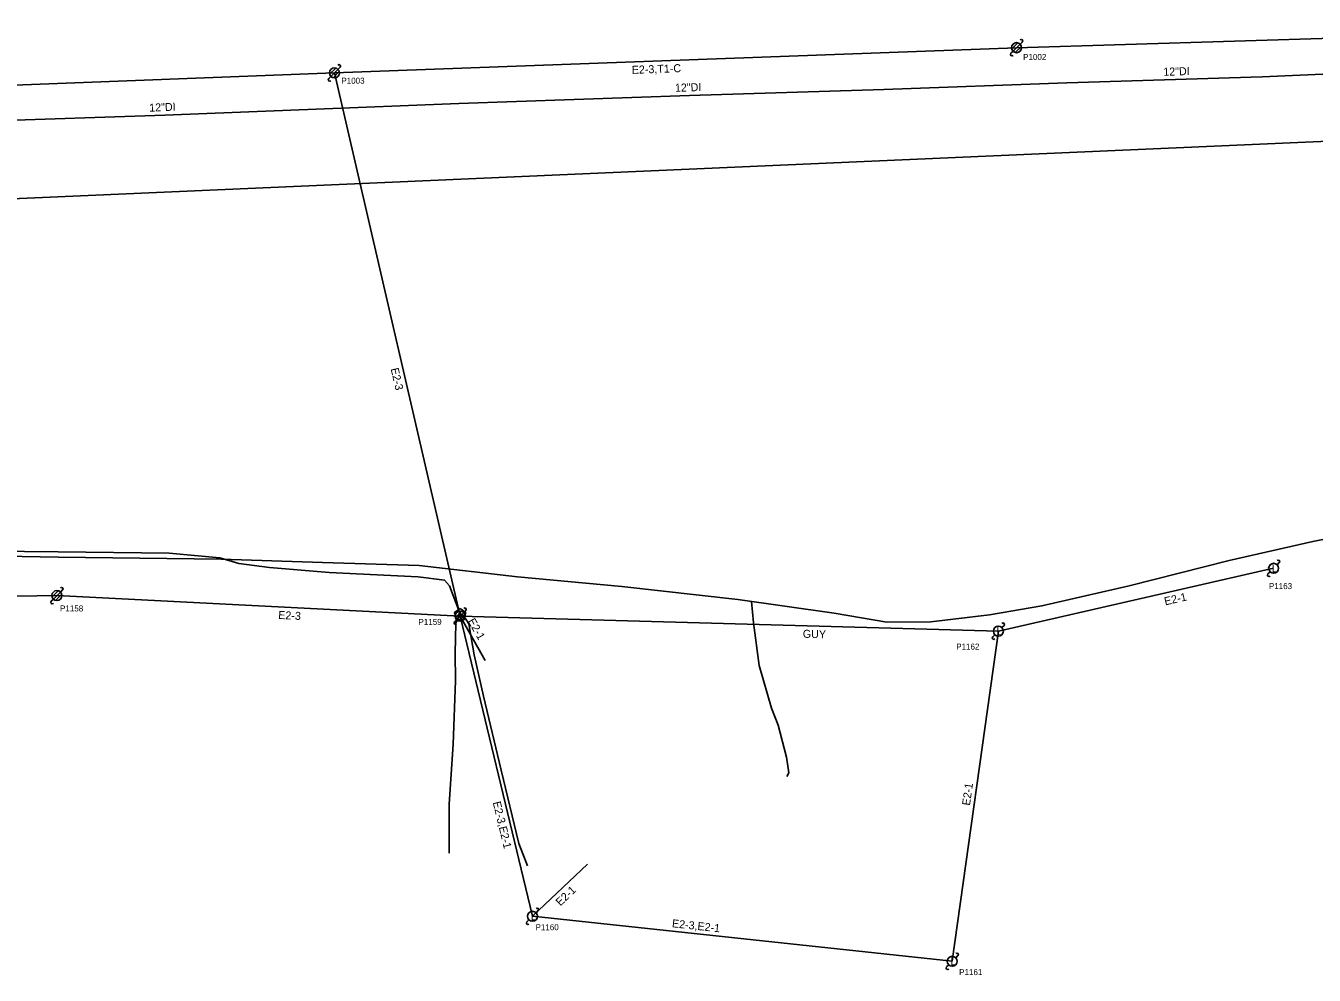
# Model space of a CAD drawing. Extents: x 1614474 to 1865144, y 1098877 to 1212550.
# Drawn here: x 1809717 to 1810361, y 1189759 to 1190233 of the extents above; entities that cross this region are included whole.
import ezdxf

# ---------------------------------------------------------------- set-up
doc = ezdxf.new("R2010")
doc.units = 0
for name, color, linetype in [('BFUSER_FIBERSPAN', 7, 'Continuous'), ('RD_EX_SU_Gas', 7, 'Continuous'), ('RD_EX_SU_H2O', 7, 'Continuous'), ('RD_EX_SU_Ovhd', 7, 'Continuous'), ('RD_EX_SU_Pole', 7, 'Continuous'), ('RD_EX_SU_Telecom', 7, 'Continuous'), ('RD_EX_SU_TX_H2O', 7, 'Continuous'), ('RD_EX_SU_TX_Pole', 7, 'Continuous')]:
    doc.layers.add(name, color=color, linetype=linetype)

# ---------------------------------------------------------------- blocks, each defined once
blk = doc.blocks.new('SUE_TPP')
at = {"layer": 'RD_EX_SU_Telecom'}
blk.add_lwpolyline([(0, 3), (-2.85, 0.93), (-1.76, -2.43), (1.76, -2.43), (2.85, 0.93)], close=True, dxfattribs=at)
blk.add_text('T', height=3.75, dxfattribs=at).set_placement((-1.25, -1.88))

msp = doc.modelspace()

# ---------------------------------------------------------------- linework, layer by layer
at = {"layer": 'BFUSER_FIBERSPAN'}
msp.add_line((1809476.93, 1190136.61), (1810575.1, 1190184.71), dxfattribs=at)
at = {"layer": 'RD_EX_SU_Gas'}
for points in [[(1809660.86, 1189969.17), (1809733.78, 1189967.7), (1809815.05, 1189966.79), (1809865.79, 1189965.14), (1809914.09, 1189963.6), (1809963.19, 1189958), (1810015.31, 1189953.17), (1810073.25, 1189946.53), (1810121.42, 1189939.86), (1810147.77, 1189935.35), (1810169.77, 1189935.43), (1810199, 1189938.9), (1810225.24, 1189943.43), (1810268.82, 1189953.37), (1810318.92, 1189966.13), (1810360.73, 1189975.64), (1810410.81, 1189985.57)], [(1810080.12, 1189945.58), (1810081.15, 1189934.9), (1810083.99, 1189913.62), (1810090.17, 1189892.36), (1810093.46, 1189883.85), (1810097.62, 1189867.87), (1810098.79, 1189859.94), (1810097.86, 1189858.14)]]:
    msp.add_lwpolyline(points, dxfattribs=at)
at = {"layer": 'RD_EX_SU_H2O'}
msp.add_lwpolyline([(1809591.04, 1190181.32), (1809610.39, 1190182.17), (1809696.97, 1190185.67), (1809786.87, 1190188.66), (1809883.54, 1190192.41), (1809933.92, 1190194.51), (1810049.07, 1190198.52), (1810146.27, 1190201.48), (1810237.73, 1190204.86), (1810335.34, 1190207.78), (1810399.91, 1190210.57), (1810447.22, 1190212.22), (1810521.22, 1190215.05), (1810575.17, 1190214.64)], dxfattribs=at)
at = {"layer": 'RD_EX_SU_Ovhd'}
for p, q in [((1810212.63, 1190222.37), (1810574.24, 1190233.31)), ((1809871.68, 1190209.77), (1810212.63, 1190222.37)), ((1809529.41, 1190196.76), (1809871.68, 1190209.77)), ((1809871.68, 1190209.77), (1809934.53, 1189938.3)), ((1810203.5, 1189930.79), (1810341.1, 1189962.2)), ((1809523.58, 1189945.02), (1809732.98, 1189948.58)), ((1809732.98, 1189948.58), (1809934.53, 1189938.3)), ((1809934.53, 1189938.3), (1810203.5, 1189930.79)), ((1809934.53, 1189938.3), (1809946.96, 1189916.2)), ((1809934.53, 1189938.3), (1809970.69, 1189788.31)), ((1810180.47, 1189765.81), (1810203.5, 1189930.79)), ((1809970.69, 1189788.31), (1809998.24, 1189814.39)), ((1809970.69, 1189788.31), (1810180.47, 1189765.81))]:
    msp.add_line(p, q, dxfattribs=at)
at = {"layer": 'RD_EX_SU_Pole'}
for p, q in [((1810209.8, 1190219.54), (1810210.86, 1190220.6)), ((1810210.21, 1190221.72), (1810213.28, 1190224.79)), ((1810210.86, 1190220.6), (1810214.4, 1190224.14)), ((1810211.98, 1190219.96), (1810215.04, 1190223.02)), ((1810214.4, 1190224.14), (1810215.46, 1190225.2)), ((1809873.45, 1190211.54), (1809874.51, 1190212.6)), ((1809868.85, 1190206.94), (1809869.91, 1190208)), ((1809869.27, 1190209.13), (1809872.33, 1190212.19)), ((1809869.91, 1190208), (1809873.45, 1190211.54)), ((1809871.03, 1190207.36), (1809874.1, 1190210.42)), ((1810342.87, 1189963.96), (1810343.93, 1189965.02)), ((1810338.27, 1189959.37), (1810339.33, 1189960.43)), ((1809730.56, 1189947.93), (1809733.62, 1189950.99)), ((1809731.21, 1189946.81), (1809734.74, 1189950.35)), ((1809732.33, 1189946.16), (1809735.39, 1189949.23)), ((1809734.74, 1189950.35), (1809735.8, 1189951.41)), ((1809730.15, 1189945.75), (1809731.21, 1189946.81)), ((1809931.7, 1189935.47), (1809932.76, 1189936.53)), ((1809932.11, 1189937.65), (1809935.18, 1189940.72)), ((1809932.76, 1189936.53), (1809936.3, 1189940.07)), ((1809933.88, 1189935.89), (1809936.94, 1189938.95)), ((1809936.3, 1189940.07), (1809937.36, 1189941.13)), ((1810205.27, 1189932.56), (1810206.33, 1189933.62)), ((1810200.67, 1189927.96), (1810201.73, 1189929.02)), ((1809972.46, 1189790.08), (1809973.52, 1189791.14)), ((1809967.86, 1189785.48), (1809968.92, 1189786.54)), ((1810182.24, 1189767.58), (1810183.3, 1189768.64)), ((1810177.64, 1189762.98), (1810178.71, 1189764.04))]:
    msp.add_line(p, q, dxfattribs=at)
for centre in [(1810212.63, 1190222.37), (1809871.68, 1190209.77), (1810341.1, 1189962.2), (1809732.98, 1189948.58), (1809934.53, 1189938.3), (1810203.5, 1189930.79), (1809970.69, 1189788.31), (1810180.47, 1189765.81)]:
    msp.add_circle(centre, 2.5, dxfattribs=at)
for centre, start, end in [((1810214.93, 1190225.73), 315, 135), ((1810210.33, 1190219.01), 135, 315), ((1809873.98, 1190213.13), 315, 135), ((1809869.38, 1190206.41), 135, 315), ((1810343.4, 1189965.55), 315, 135), ((1810338.8, 1189958.84), 135, 315), ((1809735.27, 1189951.94), 315, 135), ((1809730.68, 1189945.22), 135, 315), ((1809936.83, 1189941.66), 315, 135), ((1809932.23, 1189934.94), 135, 315), ((1810205.8, 1189934.15), 315, 135), ((1810201.2, 1189927.43), 135, 315), ((1809972.99, 1189791.67), 315, 135), ((1809968.39, 1189784.95), 135, 315), ((1810182.77, 1189769.17), 315, 135), ((1810178.18, 1189762.45), 135, 315)]:
    msp.add_arc(centre, 0.75, start, end, dxfattribs=at)
at = {"layer": 'RD_EX_SU_Telecom'}
for points in [[(1809064.57, 1189951.41), (1809108.64, 1189953.76), (1809147.32, 1189955.84), (1809193.95, 1189957.61), (1809263.77, 1189960.74), (1809333, 1189963.15), (1809412.27, 1189965.41), (1809473.17, 1189968.31), (1809509.88, 1189968.72), (1809530.26, 1189970.17), (1809576.32, 1189970.73), (1809639.66, 1189971.93), (1809682.92, 1189970.99), (1809733.59, 1189970.39), (1809789, 1189969.81), (1809814.44, 1189967.46), (1809823.87, 1189964.65), (1809839.2, 1189962.6), (1809869, 1189960.08), (1809913.46, 1189958.01), (1809926.76, 1189956.28), (1809929.27, 1189953.44), (1809934.16, 1189940.25)], [(1809933.95, 1189939.08), (1809932.32, 1189934.74), (1809932.06, 1189919.77), (1809932.14, 1189906.04), (1809931.07, 1189874.37), (1809929.1, 1189844.35), (1809929.1, 1189819.84)], [(1809934.73, 1189939.44), (1809936.22, 1189938.62), (1809938.83, 1189934.44), (1809941.59, 1189919.04), (1809946.25, 1189898.32), (1809955.03, 1189861.28), (1809963.8, 1189824.63), (1809968.2, 1189813.58)]]:
    msp.add_lwpolyline(points, dxfattribs=at)

# ---------------------------------------------------------------- block references
msp.add_blockref('SUE_TPP', (1809934.5, 1189939.12), dxfattribs=at)

# ---------------------------------------------------------------- texts
at = {"layer": 'RD_EX_SU_Ovhd'}
for s, rotation, p in [('E2-3,T1-C', 2.11634, (1810020.35, 1190209.26)), ('E2-3', 283.03466, (1809899.76, 1190061.89)), ('E2-1', 12.8575, (1810286.91, 1189943.67)), ('E2-3', 357.08132, (1809843.53, 1189936.93)), ('E2-1', 299.3622, (1809938.21, 1189935.85)), ('GUY', 358.39984, (1810105.72, 1189927.52)), ('E2-1', 82.0549, (1810189.29, 1189843.46)), ('E2-3,E2-1', 283.55562, (1809950.8, 1189845.23)), ('E2-1', 43.43479, (1809984.57, 1189793.19)), ('E2-3,E2-1', 353.87722, (1810040.25, 1189782.86))]:
    msp.add_text(s, height=4, rotation=rotation, dxfattribs=at).set_placement(p)
at = {"layer": 'RD_EX_SU_Pole'}
for p in [(1810340.24, 1189960.2), (1810202.64, 1189928.79), (1809969.83, 1189786.31), (1810179.61, 1189763.81)]:
    msp.add_text('L', height=4, dxfattribs=at).set_placement(p)
at = {"layer": 'RD_EX_SU_TX_H2O'}
for rotation, p in [(1.713, (1810286, 1190208.3)), (1.74393, (1810041.92, 1190200.3)), (2.22053, (1809779.18, 1190190.37))]:
    msp.add_text('12"DI', height=4, rotation=rotation, dxfattribs=at).set_placement(p)
at = {"layer": 'RD_EX_SU_TX_Pole'}
for s, p in [('P1002', (1810215.89, 1190216.23)), ('P1003', (1809875.15, 1190204.36)), ('P1163', (1810338.73, 1189951.8)), ('P1158', (1809734.54, 1189940.64)), ('P1159', (1809913.66, 1189933.92)), ('P1162', (1810182.44, 1189921.57)), ('P1160', (1809972.19, 1189781.36)), ('P1161', (1810183.92, 1189758.9))]:
    msp.add_text(s, height=3, dxfattribs=at).set_placement(p)

doc.saveas('drawing.dxf')
